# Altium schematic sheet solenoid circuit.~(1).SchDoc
size A; SheetNumber: 1; SheetTotal: 1
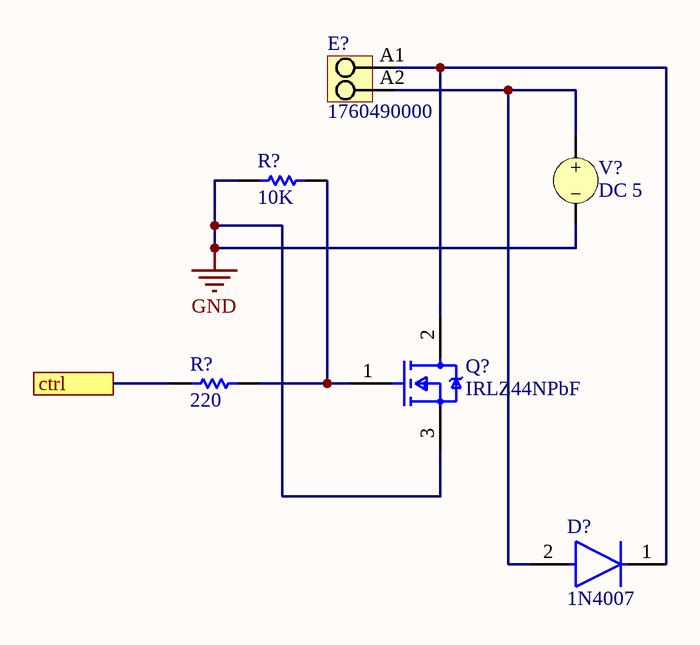
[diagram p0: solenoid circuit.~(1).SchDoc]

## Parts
(Parts that share a designator on the sheet are numbered #1, #2 ... from top to bottom, then left to right.)
D?  1N4007  [FP-1N4007-MFG]
E?  1760490000  [PM_5_08_90_02]
Q?  IRLZ44NPbF  [FP-PG-TO220-3-MFG]
R?#1  value 10K  (hidden comment: Resistor)
R?#2  value 220  (hidden comment: Resistor)
V?  DC 5

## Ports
ctrl

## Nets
GND: Q?.3(S) R?#1.1 V?.2
ctrl: R?#2.1 ; port ctrl
NetD?_1: D?.1(C) E?.A1 Q?.2(D)
NetD?_2: D?.2(A) E?.A2 V?.1
NetQ?_1: Q?.1(G) R?#1.2 R?#2.2

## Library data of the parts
D? = CMP-123542-000001-1: Rectifier diode 1000 V 1 A DO-41, ,; Manufacturer: Diotec; Max Surge Forward Current: 27A; Forward Current: 1A; Max Junction Temp: +175°C; Reverse Voltage: 1000V; Value: 15pF; Peak Reverse Current: 5uA
E? = CMP-1559-01627-1: OMNIMATE Signal - series PM; Manufacturer: Weidmueller; Contact_surface: tinned; Pitch_mm: 5,08 mm; Solid_min_H05_07_V_U: 0,13 mm²; Wire_cross_section_AWG_min_UL_1059: AWG 26; Wire_cross_section_AWG_max_UL_1059: AWG 14; Rated_voltage_for_surge_voltage_class_pollution_degree_II_2: 600 V; Rated_current_use_group_B_UL_1059: 15 A; Mounting_onto_the_PCB: Solder connection; Solder_pin_length_mm: 3,5 mm; Side_termination_characteristic: closed side; Contact_material: Cu-Leg; Pitch_inch: 0,2 inch; No_of_poles: 2; UL_94_flammability_rating: V-0; Insulating_material: Wemid (PA); Rated_voltage_use_group_B_UL_1059: 300 V; Solid_max_H05_07_V_U: 2,5 mm²; Short_text_for_material: PM 5.08/02/90 3.5SN OR BX
Q? = CMP-32901-000488-1: MOSFET N-CH 55V 47A TO220AB; Turn-On Delay Time: 11ns; Gate to Source Voltage (Vgs): 16V; Element Configuration: Single; Rds On Max: 22mR; Turn-Off Delay Time: 26ns; Max Power Dissipation: 110W; Threshold Voltage: 2V; Drain to Source Resistance: 35mR; Input Capacitance: 1.7nF
R?#1 R?#2 = Resistor: TC1: 0; SimulationGenericComponent: True
V? = VSRC: Voltage Source; Note: PCB Footprint - Not required; AC Magnitude: 1; AC Phase: 0; Value: 5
